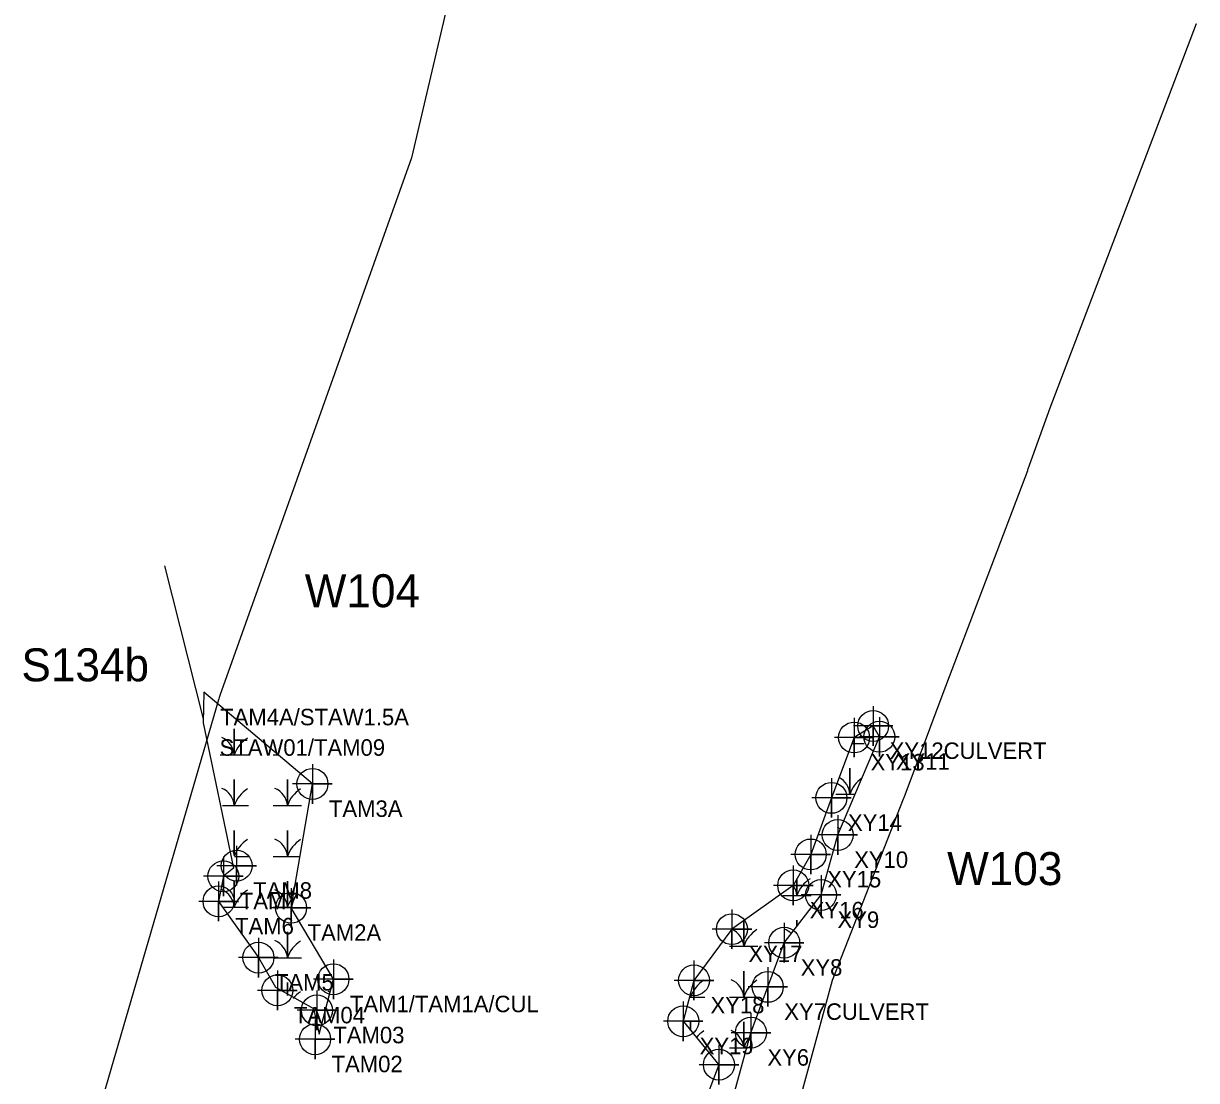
# Model space of a CAD drawing. Extents: x 1253697 to 1278588, y 912189 to 981699.
# Drawn here: x 1268800 to 1269511, y 970887 to 971529 of the extents above; entities that cross this region are included whole.
import ezdxf

# ---------------------------------------------------------------- set-up
doc = ezdxf.new("R2010")
doc.units = 0
for name, color, linetype in [('Default', 7, 'Continuous'), ('Exist Environmental Wetland Boundary', 7, 'Continuous'), ('Exist Environmental Wetland Boundary Cogo Comment', 7, 'Continuous'), ('Exist Environmental Wetland Boundary Cogo Number', 7, 'Continuous'), ('Exist Environmental Wetland Boundary Cogo Point CELL', 7, 'Continuous'), ('Exist Hydro Jurisdictional Stream or Body of Water Mitigable', 7, 'Continuous'), ('Exist Hydro Swamp or Marsh', 7, 'Continuous')]:
    doc.layers.add(name, color=color, linetype=linetype)

msp = doc.modelspace()

# ---------------------------------------------------------------- linework, layer by layer
at = {"layer": 'Default'}
for p, q in [((1269479.48, 971445.16), (1269511.23, 971528.6)), ((1269479.48, 971445.16), (1269511.23, 971528.6)), ((1268918.29, 971118.23), (1268846.94, 970873.21)), ((1268918.29, 971118.23), (1268846.94, 970873.21))]:
    msp.add_line(p, q, dxfattribs=at)
for points in [[(1269056.94, 971539.19), (1269035.39, 971447), (1268919.2, 971121.04)], [(1269056.94, 971539.19), (1269035.39, 971447), (1268919.2, 971121.04)], [(1269409.23, 971258.49), (1269422.41, 971295.53), (1269479.47, 971445.12)], [(1269409.23, 971258.49), (1269422.41, 971295.53), (1269479.47, 971445.12)], [(1269333.98, 971059.11), (1269357.54, 971122.33), (1269408.87, 971257.5)], [(1269333.98, 971059.11), (1269357.54, 971122.33), (1269408.87, 971257.5)], [(1269262.62, 970845.8), (1269290.53, 970948.32), (1269333.67, 971058.31)], [(1269262.62, 970845.8), (1269290.53, 970948.32), (1269333.67, 971058.31)]]:
    msp.add_lwpolyline(points, dxfattribs=at)
for centre, start, end in [((1269464.5, 971546.38), 339.16995, 339.22244), ((1269464.5, 971546.38), 339.16995, 339.22244), ((1269432.75, 971462.94), 339.12194, 339.16995), ((1269432.75, 971462.94), 339.12194, 339.16995), ((1269362.13, 971275.25), 339.20485, 340.4159), ((1269362.13, 971275.25), 339.20485, 340.4159), ((1268966.3, 971104.26), 160.38015, 163.7657), ((1268966.3, 971104.26), 160.38015, 163.7657), ((1269287.12, 971076.56), 338.58384, 339.56494), ((1269287.12, 971076.56), 338.58384, 339.56494)]:
    msp.add_arc(centre, 50, start, end, dxfattribs=at)
at = {"layer": 'Exist Environmental Wetland Boundary'}
msp.add_lwpolyline([(1268909.32, 971122.88), (1268908.98, 971104.4), (1268927.49, 971016.24), (1268921.24, 971011.28), (1268918.35, 970996.07), (1268942.51, 970961.96), (1268952.84, 970944.12), (1268975.86, 970931.04), (1268979.35, 970915.47), (1268987.99, 970948.84), (1268962.34, 970992.16), (1268975.27, 971067.33)], close=True, dxfattribs=at)
msp.add_lwpolyline([(1269229.72, 970875.14), (1269241.07, 970916.42), (1269251.32, 970944.22), (1269261.26, 970971), (1269283.61, 970999.96), (1269293.69, 971036.38), (1269318.94, 971095.91), (1269315.2, 971102.48), (1269303.66, 971095.47), (1269289.92, 971058.86), (1269277.37, 971024.52), (1269266.75, 971005.78), (1269229.55, 970979.22), (1269206.56, 970948.16), (1269200.03, 970923.34), (1269221.69, 970897), (1269200.94, 970842.71)], dxfattribs=at)
at = {"layer": 'Exist Environmental Wetland Boundary Cogo Point CELL'}
for points in [[(1269315.2, 971114.48), (1269315.2, 971090.48), (1269315.2, 971102.48), (1269327.2, 971102.48), (1269303.2, 971102.48)], [(1269303.66, 971107.47), (1269303.66, 971083.47), (1269303.66, 971095.47), (1269315.66, 971095.47), (1269291.66, 971095.47)], [(1269318.94, 971107.91), (1269318.94, 971083.91), (1269318.94, 971095.91), (1269330.94, 971095.91), (1269306.94, 971095.91)], [(1268975.27, 971079.33), (1268975.27, 971055.33), (1268975.27, 971067.33), (1268987.27, 971067.33), (1268963.27, 971067.33)], [(1269289.92, 971070.86), (1269289.92, 971046.86), (1269289.92, 971058.86), (1269301.92, 971058.86), (1269277.92, 971058.86)], [(1269293.69, 971048.38), (1269293.69, 971024.38), (1269293.69, 971036.38), (1269305.69, 971036.38), (1269281.69, 971036.38)], [(1269277.37, 971036.52), (1269277.37, 971012.52), (1269277.37, 971024.52), (1269289.37, 971024.52), (1269265.37, 971024.52)], [(1268929.32, 971029.7), (1268929.32, 971005.7), (1268929.32, 971017.7), (1268941.32, 971017.7), (1268917.32, 971017.7)], [(1268921.24, 971023.28), (1268921.24, 970999.28), (1268921.24, 971011.28), (1268933.24, 971011.28), (1268909.24, 971011.28)], [(1269266.75, 971017.78), (1269266.75, 970993.78), (1269266.75, 971005.78), (1269278.75, 971005.78), (1269254.75, 971005.78)], [(1269283.61, 971011.96), (1269283.61, 970987.96), (1269283.61, 970999.96), (1269295.61, 970999.96), (1269271.61, 970999.96)], [(1268918.35, 971008.07), (1268918.35, 970984.07), (1268918.35, 970996.07), (1268930.35, 970996.07), (1268906.35, 970996.07)], [(1268962.34, 971004.16), (1268962.34, 970980.16), (1268962.34, 970992.16), (1268974.34, 970992.16), (1268950.34, 970992.16)], [(1269229.55, 970991.22), (1269229.55, 970967.22), (1269229.55, 970979.22), (1269241.55, 970979.22), (1269217.55, 970979.22)], [(1269261.26, 970983), (1269261.26, 970959), (1269261.26, 970971), (1269273.26, 970971), (1269249.26, 970971)], [(1268942.51, 970973.96), (1268942.51, 970949.96), (1268942.51, 970961.96), (1268954.51, 970961.96), (1268930.51, 970961.96)], [(1268987.99, 970960.84), (1268987.99, 970936.84), (1268987.99, 970948.84), (1268999.99, 970948.84), (1268975.99, 970948.84)], [(1268954.02, 970954.09), (1268954.02, 970930.09), (1268954.02, 970942.09), (1268966.02, 970942.09), (1268942.02, 970942.09)], [(1269206.56, 970960.16), (1269206.56, 970936.16), (1269206.56, 970948.16), (1269218.56, 970948.16), (1269194.56, 970948.16)], [(1269251.32, 970956.22), (1269251.32, 970932.22), (1269251.32, 970944.22), (1269263.32, 970944.22), (1269239.32, 970944.22)], [(1268977.95, 970941.99), (1268977.95, 970917.99), (1268977.95, 970929.99), (1268989.95, 970929.99), (1268965.95, 970929.99)], [(1269200.03, 970935.34), (1269200.03, 970911.34), (1269200.03, 970923.34), (1269212.03, 970923.34), (1269188.03, 970923.34)], [(1269241.07, 970928.42), (1269241.07, 970904.42), (1269241.07, 970916.42), (1269253.07, 970916.42), (1269229.07, 970916.42)], [(1268976.87, 970924.45), (1268976.87, 970900.45), (1268976.87, 970912.45), (1268988.87, 970912.45), (1268964.87, 970912.45)], [(1269221.69, 970909), (1269221.69, 970885), (1269221.69, 970897), (1269233.69, 970897), (1269209.69, 970897)]]:
    msp.add_lwpolyline(points, dxfattribs=at)
for centre in [(1269315.2, 971102.48), (1269303.66, 971095.47), (1269318.94, 971095.91), (1268975.27, 971067.33), (1269289.92, 971058.86), (1269293.69, 971036.38), (1269277.37, 971024.52), (1268929.32, 971017.7), (1268921.24, 971011.28), (1269266.75, 971005.78), (1268918.35, 970996.07), (1269283.61, 970999.96), (1268962.34, 970992.16), (1269229.55, 970979.22), (1269261.26, 970971), (1268942.51, 970961.96), (1268987.99, 970948.84), (1269206.56, 970948.16), (1269251.32, 970944.22), (1268954.02, 970942.09), (1268977.95, 970929.99), (1269200.03, 970923.34), (1269241.07, 970916.42), (1268976.87, 970912.45), (1269221.69, 970897)]:
    msp.add_circle(centre, 9.38, dxfattribs=at)
at = {"layer": 'Exist Hydro Jurisdictional Stream or Body of Water Mitigable'}
msp.add_line((1268885.63, 971199.57), (1268909.02, 971106.75), dxfattribs=at)
at = {"layer": 'Exist Hydro Swamp or Marsh'}
for p, q in [((1269302.33, 971091.93), (1269309.75, 971091.93)), ((1268951.49, 971084.92), (1268954.38, 971084.92)), ((1268928, 971023.36), (1268936.49, 971023.36)), ((1269260.35, 970968.81), (1269260.45, 970968.81))]:
    msp.add_line(p, q, dxfattribs=at)
for points in [[(1268919.29, 971084.92), (1268927.89, 971084.92), (1268927.89, 971100.7), (1268927.89, 971084.92), (1268936.49, 971084.92)], [(1269292.55, 971061.15), (1269301.15, 971061.15), (1269301.15, 971076.93), (1269301.15, 971061.15), (1269304.2, 971061.15)], [(1268920.77, 971054.14), (1268927.89, 971054.14), (1268927.89, 971069.92), (1268927.89, 971054.14), (1268936.49, 971054.14)], [(1268951.49, 971054.14), (1268960.09, 971054.14), (1268960.09, 971069.92), (1268960.09, 971054.14), (1268968.7, 971054.14)], [(1268927.89, 971023.8), (1268927.89, 971039.14), (1268927.89, 971023.8)], [(1268951.49, 971023.36), (1268960.09, 971023.36), (1268960.09, 971039.14), (1268960.09, 971023.36), (1268967.71, 971023.36)], [(1268920.82, 970992.58), (1268927.89, 970992.58), (1268927.89, 971008.36), (1268927.89, 970992.58), (1268936.49, 970992.58)], [(1268951.49, 970992.58), (1268960.09, 970992.58), (1268960.09, 971008.36), (1268960.09, 970992.58), (1268962.41, 970992.58)], [(1269260.35, 970999.59), (1269268.95, 970999.59), (1269268.95, 971009.65)], [(1269268.95, 971009.65), (1269268.95, 970999.59), (1269277.55, 970999.59)], [(1269228.14, 970968.81), (1269236.74, 970968.81), (1269236.74, 970984.36)], [(1269236.74, 970984.36), (1269236.74, 970968.81), (1269245.35, 970968.81)], [(1269268.95, 970980.96), (1269268.95, 970984.59), (1269268.95, 970980.96)], [(1268951.49, 970961.8), (1268960.09, 970961.8), (1268960.09, 970977.58), (1268960.09, 970961.8), (1268968.7, 970961.8)], [(1269228.14, 970938.03), (1269236.74, 970938.03), (1269236.74, 970953.81), (1269236.74, 970938.03), (1269245.35, 970938.03)], [(1268960.09, 970939.01), (1268960.09, 970946.8), (1268960.09, 970939.01)], [(1269203.89, 970938.03), (1269204.54, 970938.03), (1269204.54, 970940.49)], [(1269204.54, 970940.49), (1269204.54, 970938.03), (1269213.14, 970938.03)], [(1269204.54, 970917.85), (1269204.54, 970923.03), (1269204.54, 970917.85)], [(1269228.14, 970907.25), (1269236.74, 970907.25), (1269236.74, 970923.03), (1269236.74, 970907.25), (1269238.55, 970907.25)]]:
    msp.add_lwpolyline(points, dxfattribs=at)
for centre, radius, start, end in [((1268915.62, 971084.03), 12.3, 4.14034, 67.53497), ((1268946.13, 971078.86), 19.22, 122.12745, 161.62219), ((1269288.88, 971060.26), 12.3, 4.14034, 62.59904), ((1269319.39, 971055.09), 19.22, 125.31394, 161.62219), ((1268915.62, 971053.25), 12.3, 4.14034, 67.53497), ((1268946.13, 971048.08), 19.22, 122.12745, 161.62219), ((1268947.83, 971053.25), 12.3, 4.14034, 67.53497), ((1268978.34, 971048.08), 19.22, 122.12745, 161.62219), ((1269288.88, 971029.48), 12.3, 58.91058, 67.53497), ((1268946.13, 971017.3), 19.22, 122.12745, 161.04699), ((1268947.83, 971022.47), 12.3, 4.14034, 67.53497), ((1268978.34, 971017.3), 19.22, 122.12745, 161.62219), ((1268915.62, 971022.47), 12.3, 7.94812, 18.46662), ((1269256.68, 970998.7), 12.3, 4.14034, 35.09444), ((1269287.19, 970993.53), 19.22, 122.12745, 161.62219), ((1268915.62, 970991.69), 12.3, 4.14034, 67.53497), ((1268946.13, 970986.52), 19.22, 122.12745, 161.62219), ((1268947.83, 970991.69), 12.3, 4.14034, 67.53497), ((1268978.34, 970986.52), 19.22, 140.67553, 161.62219), ((1269224.48, 970967.92), 12.3, 4.14034, 65.91881), ((1269254.99, 970962.75), 19.22, 122.12745, 161.62219), ((1269256.68, 970967.92), 12.3, 44.19536, 67.53497), ((1268946.13, 970955.74), 19.22, 122.12745, 123.41074), ((1268947.83, 970960.91), 12.3, 4.14034, 67.53497), ((1268978.34, 970955.74), 19.22, 122.12745, 161.62219), ((1269222.78, 970931.97), 19.22, 122.12745, 161.62219), ((1269224.48, 970937.14), 12.3, 4.14034, 67.53497), ((1269254.99, 970931.97), 19.22, 122.12745, 161.62219), ((1268978.34, 970924.96), 19.22, 122.12745, 140.20603), ((1268980.03, 970930.13), 12.3, 61.29367, 67.53497), ((1269192.27, 970937.14), 12.3, 4.14034, 11.71561), ((1269222.78, 970901.19), 19.22, 122.12745, 139.93277), ((1269224.48, 970906.36), 12.3, 4.14034, 67.53497), ((1269254.99, 970901.19), 19.22, 139.88523, 161.62219)]:
    msp.add_arc(centre, radius, start, end, dxfattribs=at)

# ---------------------------------------------------------------- texts
at = {"layer": 'Exist Environmental Wetland Boundary'}
msp.add_text('S134b', height=20, dxfattribs=at).set_placement((1268798.85, 971129.56))
at = {"layer": 'Exist Environmental Wetland Boundary Cogo Comment'}
for s, p in [('TAM4A/STAW1.5A', (1268919.32, 971102.88)), ('STAW01/TAM09', (1268918.98, 971084.4)), ('XY12CULVERT', (1269325.2, 971082.48)), ('XY13', (1269313.66, 971075.47)), ('XY11', (1269328.94, 971075.91)), ('TAM3A', (1268985.27, 971047.33)), ('XY14', (1269299.92, 971038.86)), ('XY10', (1269303.69, 971016.38)), ('XY15', (1269287.37, 971004.52)), ('TAM8', (1268939.32, 970997.7)), ('TAM7', (1268931.24, 970991.28)), ('XY16', (1269276.75, 970985.78)), ('XY9', (1269293.61, 970979.96)), ('TAM6', (1268928.35, 970976.07)), ('TAM2A', (1268972.34, 970972.16)), ('XY17', (1269239.55, 970959.22)), ('XY8', (1269271.26, 970951)), ('TAM5', (1268952.51, 970941.96)), ('TAM1/TAM1A/CUL', (1268997.99, 970928.84)), ('TAM04', (1268964.02, 970922.09)), ('XY18', (1269216.56, 970928.16)), ('XY7CULVERT', (1269261.32, 970924.22)), ('TAM03', (1268987.95, 970909.99)), ('XY19', (1269210.03, 970903.34)), ('XY6', (1269251.07, 970896.42)), ('TAM02', (1268986.87, 970892.45))]:
    msp.add_text(s, height=10, dxfattribs=at).set_placement(p)
at = {"layer": 'Exist Environmental Wetland Boundary Cogo Number'}
for s, p in [('W104', (1268970.62, 971174.49)), ('W103', (1269360.05, 971005.94))]:
    msp.add_text(s, height=20, dxfattribs=at).set_placement(p)

doc.saveas('drawing.dxf')
